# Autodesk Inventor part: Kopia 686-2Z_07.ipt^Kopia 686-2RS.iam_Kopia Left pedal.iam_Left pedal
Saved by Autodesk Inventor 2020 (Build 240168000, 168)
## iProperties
Created: 2017-10
Part Number: Kopia 686-2Z_07.ipt^Kopia 686-2RS.iam_Kopia Left pedal.iam_Left pedal
Material: Ogólny
Document SubType Name: Modeling
Designer: Tomasz
Density: 1 g/cm^3
Appearance: Domyślna
Sending System: SolidWorks 2017
Last Author: Tomasz
Last Saved: 2017-10-01
Author: Tomasz
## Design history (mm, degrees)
